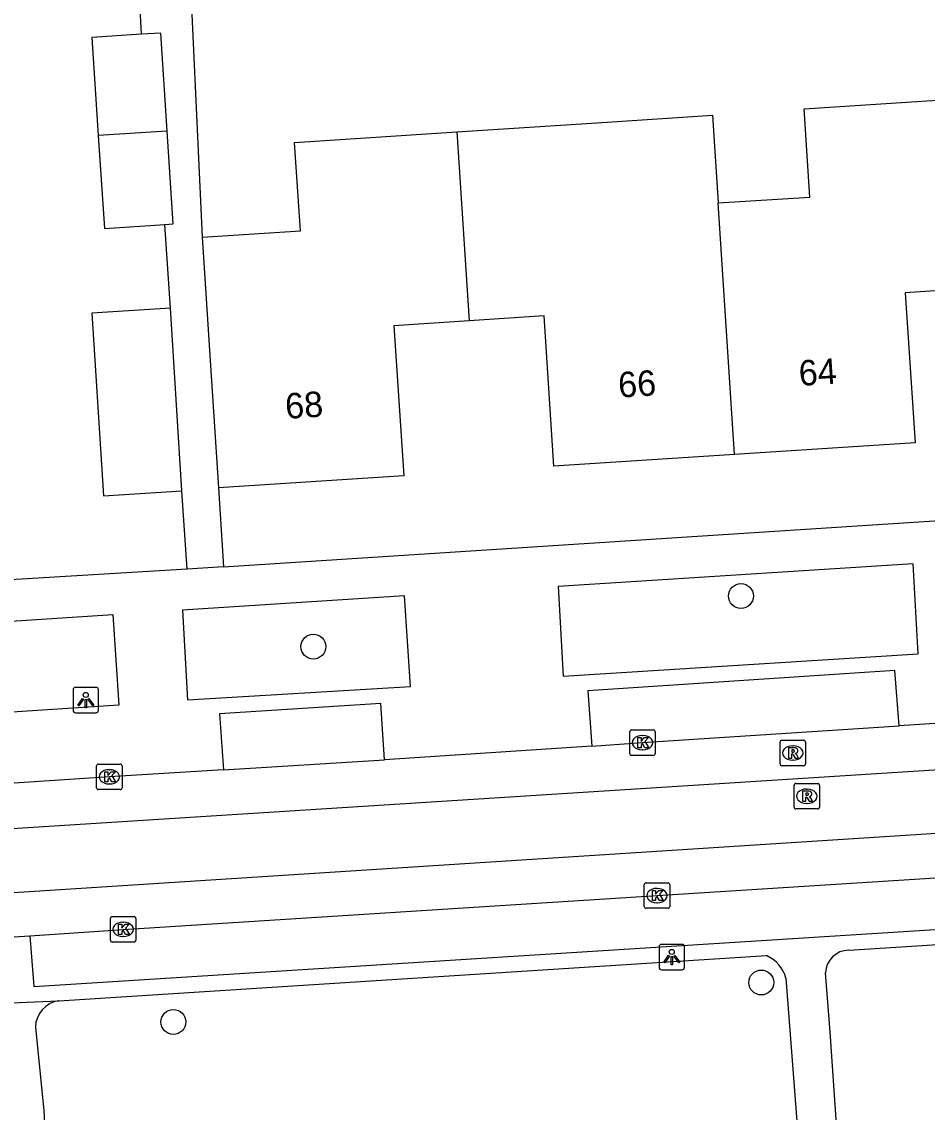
# Model space of a CAD drawing. Extents: x 159689 to 160786, y 387323 to 388339.
# Drawn here: x 160255.13 to 160290.64, y 388015.99 to 388058.78 of the extents above; entities that cross this region are included whole.
import ezdxf

# ---------------------------------------------------------------- set-up
doc = ezdxf.new("R2010")
doc.units = 0
for name, color, linetype in [('IMGEO_Boom', 7, 'Continuous'), ('IMGEO_Kolk', 7, 'Continuous'), ('IMGEO_Lichtpunt', 7, 'Continuous'), ('IMGEO_Pand', 7, 'Continuous'), ('IMGEO_Pand_nummerreeks', 7, 'Continuous'), ('IMGEO_Rijbaan_lokaal_gesloten', 7, 'Continuous'), ('IMGEO_Rioolput', 7, 'Continuous'), ('IMGEO_Voetpad_open', 7, 'Continuous')]:
    doc.layers.add(name, color=color, linetype=linetype)

msp = doc.modelspace()

# ---------------------------------------------------------------- linework, layer by layer
at = {"layer": 'IMGEO_Boom'}
for centre in [(160283.337, 388036.249), (160266.564, 388034.262), (160284.133, 388021.082), (160261.072, 388019.532)]:
    msp.add_circle(centre, 0.489, dxfattribs=at)
at = {"layer": 'IMGEO_Kolk'}
for p, q in [((160278.972, 388030.068), (160278.972, 388030.92)), ((160279.047, 388030.994), (160279.899, 388030.994)), ((160279.46, 388030.774), (160279.485, 388030.774)), ((160279.973, 388030.92), (160279.973, 388030.068)), ((160279.483, 388030.214), (160279.458, 388030.214)), ((160279.899, 388029.994), (160279.047, 388029.994)), ((160258.063, 388028.727), (160258.063, 388029.579)), ((160258.138, 388029.653), (160258.99, 388029.653)), ((160258.551, 388029.433), (160258.576, 388029.433)), ((160259.064, 388029.579), (160259.064, 388028.727)), ((160258.99, 388028.653), (160258.138, 388028.653)), ((160258.574, 388028.873), (160258.549, 388028.873)), ((160279.544, 388024.068), (160279.544, 388024.92)), ((160279.619, 388024.994), (160280.471, 388024.994)), ((160280.032, 388024.774), (160280.057, 388024.774)), ((160280.545, 388024.92), (160280.545, 388024.068)), ((160280.055, 388024.214), (160280.03, 388024.214)), ((160280.471, 388023.994), (160279.619, 388023.994)), ((160258.602, 388022.741), (160258.602, 388023.593)), ((160258.677, 388023.667), (160259.529, 388023.667)), ((160259.09, 388023.447), (160259.115, 388023.447)), ((160259.603, 388023.593), (160259.603, 388022.741)), ((160259.113, 388022.887), (160259.088, 388022.887)), ((160259.529, 388022.667), (160258.677, 388022.667))]:
    msp.add_line(p, q, dxfattribs=at)
for points in [[(160278.972, 388030.068), (160278.972, 388030.92)], [(160279.047, 388030.994), (160279.899, 388030.994)], [(160279.293, 388030.694), (160279.416, 388030.694), (160279.416, 388030.543), (160279.546, 388030.694), (160279.71, 388030.694), (160279.564, 388030.543), (160279.717, 388030.294), (160279.565, 388030.294), (160279.48, 388030.458), (160279.416, 388030.391), (160279.416, 388030.294), (160279.293, 388030.294), (160279.293, 388030.694)], [(160279.973, 388030.92), (160279.973, 388030.068)], [(160279.899, 388029.994), (160279.047, 388029.994)], [(160258.063, 388028.727), (160258.063, 388029.579)], [(160258.138, 388029.653), (160258.99, 388029.653)], [(160258.384, 388029.353), (160258.507, 388029.353), (160258.507, 388029.202), (160258.637, 388029.353), (160258.801, 388029.353), (160258.655, 388029.202), (160258.808, 388028.953), (160258.656, 388028.953), (160258.571, 388029.117), (160258.507, 388029.05), (160258.507, 388028.953), (160258.384, 388028.953), (160258.384, 388029.353)], [(160259.064, 388029.579), (160259.064, 388028.727)], [(160258.99, 388028.653), (160258.138, 388028.653)], [(160279.544, 388024.068), (160279.544, 388024.92)], [(160279.619, 388024.994), (160280.471, 388024.994)], [(160279.865, 388024.694), (160279.988, 388024.694), (160279.988, 388024.543), (160280.118, 388024.694), (160280.282, 388024.694), (160280.136, 388024.543), (160280.289, 388024.294), (160280.137, 388024.294), (160280.052, 388024.458), (160279.988, 388024.391), (160279.988, 388024.294), (160279.865, 388024.294), (160279.865, 388024.694)], [(160280.545, 388024.92), (160280.545, 388024.068)], [(160280.471, 388023.994), (160279.619, 388023.994)], [(160258.602, 388022.741), (160258.602, 388023.593)], [(160258.677, 388023.667), (160259.529, 388023.667)], [(160258.923, 388023.367), (160259.046, 388023.367), (160259.046, 388023.216), (160259.176, 388023.367), (160259.34, 388023.367), (160259.194, 388023.216), (160259.347, 388022.967), (160259.195, 388022.967), (160259.11, 388023.131), (160259.046, 388023.064), (160259.046, 388022.967), (160258.923, 388022.967), (160258.923, 388023.367)], [(160259.603, 388023.593), (160259.603, 388022.741)], [(160259.529, 388022.667), (160258.677, 388022.667)]]:
    msp.add_lwpolyline(points, dxfattribs=at)
for centre, start, end in [((160279.049, 388030.918), 91.552, 178.448), ((160279.049, 388030.918), 91.552, 178.448), ((160279.897, 388030.918), 1.552, 88.448), ((160279.897, 388030.918), 1.552, 88.448), ((160279.049, 388030.07), 181.552, 268.448), ((160279.049, 388030.07), 181.552, 268.448), ((160279.897, 388030.07), 271.552, 358.448), ((160279.897, 388030.07), 271.552, 358.448), ((160258.14, 388029.577), 91.552, 178.448), ((160258.14, 388029.577), 91.552, 178.448), ((160258.988, 388029.577), 1.552, 88.448), ((160258.988, 388029.577), 1.552, 88.448), ((160258.14, 388028.729), 181.552, 268.448), ((160258.14, 388028.729), 181.552, 268.448), ((160258.988, 388028.729), 271.552, 358.448), ((160258.988, 388028.729), 271.552, 358.448), ((160279.621, 388024.918), 91.552, 178.448), ((160279.621, 388024.918), 91.552, 178.448), ((160280.469, 388024.918), 1.552, 88.448), ((160280.469, 388024.918), 1.552, 88.448), ((160279.621, 388024.07), 181.552, 268.448), ((160279.621, 388024.07), 181.552, 268.448), ((160280.469, 388024.07), 271.552, 358.448), ((160280.469, 388024.07), 271.552, 358.448), ((160258.679, 388023.591), 91.552, 178.448), ((160258.679, 388023.591), 91.552, 178.448), ((160259.527, 388023.591), 1.552, 88.448), ((160259.527, 388023.591), 1.552, 88.448), ((160258.679, 388022.743), 181.552, 268.448), ((160258.679, 388022.743), 181.552, 268.448), ((160259.527, 388022.743), 271.552, 358.448), ((160259.527, 388022.743), 271.552, 358.448)]:
    msp.add_arc(centre, 0.0765, start, end, dxfattribs=at)
for centre, major_axis, ratio, start_param, end_param in [((160279.459, 388030.494), (-0.387, 0.002), 0.722429, 4.712389, 7.853982), ((160279.484, 388030.494), (-0.39, 0.002), 0.717154, 1.570796, 4.712389), ((160258.55, 388029.153), (-0.387, 0.002), 0.722429, 4.712389, 7.853982), ((160258.575, 388029.153), (-0.39, 0.002), 0.717154, 1.570796, 4.712389), ((160280.031, 388024.494), (-0.387, 0.002), 0.722429, 4.712389, 7.853982), ((160280.056, 388024.494), (-0.39, 0.002), 0.717154, 1.570796, 4.712389), ((160259.089, 388023.167), (-0.387, 0.002), 0.722429, 4.712389, 7.853982), ((160259.114, 388023.167), (-0.39, 0.002), 0.717154, 1.570796, 4.712389)]:
    msp.add_ellipse(centre, major_axis=major_axis, ratio=ratio, start_param=start_param, end_param=end_param, dxfattribs=at)
at = {"layer": 'IMGEO_Lichtpunt'}
for p, q in [((160257.137, 388032.568), (160257.137, 388031.761)), ((160257.137, 388032.568), (160257.137, 388031.761)), ((160258.039, 388032.663), (160257.231, 388032.663)), ((160258.039, 388032.663), (160257.231, 388032.663)), ((160258.133, 388031.761), (160258.133, 388032.568)), ((160258.133, 388031.761), (160258.133, 388032.568)), ((160257.231, 388031.667), (160258.039, 388031.667)), ((160257.231, 388031.667), (160258.039, 388031.667)), ((160280.123, 388022.484), (160280.123, 388021.677)), ((160280.123, 388022.484), (160280.123, 388021.677)), ((160281.025, 388022.579), (160280.217, 388022.579)), ((160281.025, 388022.579), (160280.217, 388022.579)), ((160281.119, 388021.677), (160281.119, 388022.484)), ((160281.119, 388021.677), (160281.119, 388022.484)), ((160280.217, 388021.583), (160281.025, 388021.583)), ((160280.217, 388021.583), (160281.025, 388021.583))]:
    msp.add_line(p, q, dxfattribs=at)
for points in [[(160257.511, 388032.232), (160257.55, 388032.204), (160257.362, 388031.942), (160257.324, 388031.969), (160257.511, 388032.232)], [(160257.613, 388032.184), (160257.66, 388032.184), (160257.66, 388031.862), (160257.613, 388031.862), (160257.613, 388032.184)], [(160257.723, 388032.204), (160257.761, 388032.231), (160257.948, 388031.969), (160257.909, 388031.941), (160257.723, 388032.204)], [(160280.497, 388022.148), (160280.536, 388022.12), (160280.348, 388021.858), (160280.31, 388021.885), (160280.497, 388022.148)], [(160280.599, 388022.1), (160280.646, 388022.1), (160280.646, 388021.778), (160280.599, 388021.778), (160280.599, 388022.1)], [(160280.709, 388022.12), (160280.747, 388022.147), (160280.934, 388021.885), (160280.895, 388021.857), (160280.709, 388022.12)]]:
    msp.add_lwpolyline(points, dxfattribs=at)
for centre in [(160257.636, 388032.366), (160280.622, 388022.282)]:
    msp.add_circle(centre, 0.0994, dxfattribs=at)
for centre, start, end in [((160257.231, 388032.568), 90, 180), ((160257.231, 388032.568), 90, 180), ((160258.039, 388032.568), 0, 90), ((160258.039, 388032.568), 0, 90), ((160257.231, 388031.761), 180, 270), ((160257.231, 388031.761), 180, 270), ((160258.039, 388031.761), 270, 0), ((160258.039, 388031.761), 270, 360), ((160280.217, 388022.484), 90, 180), ((160280.217, 388022.484), 90, 180), ((160281.025, 388022.484), 0, 90), ((160281.025, 388022.484), 0, 90), ((160280.217, 388021.677), 180, 270), ((160280.217, 388021.677), 180, 270), ((160281.025, 388021.677), 270, 0), ((160281.025, 388021.677), 270, 360)]:
    msp.add_arc(centre, 0.0946, start, end, dxfattribs=at)
at = {"layer": 'IMGEO_Pand'}
for points in [[(160259.824, 388058.292), (160257.874, 388058.163), (160258.128, 388054.325)], [(160260.829, 388054.497), (160260.575, 388058.341), (160259.824, 388058.292)], [(160282.441, 388051.673), (160286.037, 388051.907), (160285.812, 388055.369), (160292.23, 388055.786)], [(160272.192, 388054.462), (160278.093, 388054.845), (160282.217, 388055.113), (160282.441, 388051.673)], [(160260.829, 388054.497), (160258.128, 388054.325)], [(160258.128, 388054.325), (160258.369, 388050.674), (160260.738, 388050.83)], [(160260.738, 388050.83), (160261.07, 388050.852), (160260.829, 388054.497)], [(160262.203, 388050.335), (160266.054, 388050.585), (160265.829, 388054.048), (160272.192, 388054.462)], [(160272.192, 388054.462), (160272.67, 388047.05)], [(160283.082, 388041.799), (160282.441, 388051.673)], [(160262.203, 388050.335), (160262.518, 388045.489), (160262.843, 388040.499)], [(160292.718, 388048.337), (160289.781, 388048.146), (160290.163, 388042.259), (160283.082, 388041.799)], [(160260.954, 388047.55), (160257.874, 388047.354), (160258.33, 388040.177), (160261.41, 388040.373)], [(160261.41, 388040.373), (160260.954, 388047.55)], [(160272.67, 388047.05), (160269.724, 388046.858), (160270.107, 388040.971), (160262.843, 388040.499)], [(160283.082, 388041.799), (160275.998, 388041.338), (160275.614, 388047.241), (160272.67, 388047.05)]]:
    msp.add_lwpolyline(points, dxfattribs=at)
at = {"layer": 'IMGEO_Rijbaan_lokaal_gesloten'}
for points in [[(160245.491, 388026.537), (160290.916, 388029.427), (160338.317, 388032.462), (160338.195, 388034.165)], [(160297.65, 388031.683), (160297.399, 388031.668), (160289.544, 388031.148)], [(160277.493, 388030.35), (160279.473, 388030.494), (160289.544, 388031.148)], [(160277.493, 388030.35), (160269.356, 388029.816)], [(160338.592, 388028.187), (160338.462, 388029.906), (160303.208, 388027.708), (160245.653, 388024.011)], [(160263.039, 388029.425), (160269.356, 388029.816)], [(160263.039, 388029.425), (160258.564, 388029.153), (160245.382, 388028.282)], [(160255.446, 388022.909), (160259.103, 388023.167), (160280.045, 388024.494), (160297.975, 388025.628), (160338.592, 388028.187)], [(160245.738, 388022.293), (160255.446, 388022.909)]]:
    msp.add_lwpolyline(points, dxfattribs=at)
at = {"layer": 'IMGEO_Rioolput'}
for p, q in [((160284.943, 388030.588), (160285.795, 388030.588)), ((160284.868, 388029.662), (160284.868, 388030.514)), ((160285.356, 388030.368), (160285.381, 388030.368)), ((160285.869, 388030.514), (160285.869, 388029.662)), ((160285.379, 388029.808), (160285.354, 388029.808)), ((160285.795, 388029.588), (160284.943, 388029.588)), ((160285.493, 388028.892), (160286.345, 388028.892)), ((160285.418, 388027.966), (160285.418, 388028.818)), ((160285.906, 388028.672), (160285.931, 388028.672)), ((160286.419, 388028.818), (160286.419, 388027.966)), ((160285.929, 388028.112), (160285.904, 388028.112)), ((160286.345, 388027.892), (160285.493, 388027.892))]:
    msp.add_line(p, q, dxfattribs=at)
for points in [[(160284.943, 388030.588), (160285.795, 388030.588)], [(160284.868, 388029.662), (160284.868, 388030.514)], [(160285.457, 388030.286), (160285.205, 388030.288), (160285.205, 388029.888)], [(160285.383, 388030.207), (160285.329, 388030.207), (160285.329, 388030.126)], [(160285.869, 388030.514), (160285.869, 388029.662)], [(160285.205, 388029.888), (160285.329, 388029.888), (160285.329, 388030.05), (160285.34, 388030.05)], [(160285.329, 388030.126), (160285.381, 388030.126)], [(160285.387, 388030.021), (160285.458, 388029.888), (160285.598, 388029.888), (160285.533, 388030.014)], [(160285.795, 388029.588), (160284.943, 388029.588)], [(160285.493, 388028.892), (160286.345, 388028.892)], [(160285.418, 388027.966), (160285.418, 388028.818)], [(160286.007, 388028.59), (160285.755, 388028.592), (160285.755, 388028.192)], [(160285.933, 388028.511), (160285.879, 388028.511), (160285.879, 388028.43)], [(160286.419, 388028.818), (160286.419, 388027.966)], [(160285.755, 388028.192), (160285.879, 388028.192), (160285.879, 388028.354), (160285.89, 388028.354)], [(160285.879, 388028.43), (160285.931, 388028.43)], [(160285.937, 388028.325), (160286.008, 388028.192), (160286.148, 388028.192), (160286.083, 388028.318)], [(160286.345, 388027.892), (160285.493, 388027.892)]]:
    msp.add_lwpolyline(points, dxfattribs=at)
for centre, radius, start, end in [((160284.945, 388030.512), 0.0765, 91.552, 178.448), ((160284.945, 388030.512), 0.0765, 91.552, 178.448), ((160285.793, 388030.512), 0.0765, 1.552, 88.448), ((160285.793, 388030.512), 0.0765, 1.552, 88.448), ((160285.389, 388030.111), 0.0964, 77.0061, 93.1865), ((160285.403, 388030.168), 0.0378, 276.6634, 79.6772), ((160285.456, 388030.176), 0.109, 350.3612, 89.416), ((160285.339, 388029.997), 0.0533, 26.0293, 88.6989), ((160285.365, 388030.315), 0.19, 274.7715, 282.9687), ((160285.454, 388030.176), 0.112, 277.5842, 350.9817), ((160285.438, 388029.961), 0.108, 29.5134, 73.7905), ((160284.945, 388029.664), 0.0765, 181.552, 268.448), ((160284.945, 388029.664), 0.0765, 181.552, 268.448), ((160285.793, 388029.664), 0.0765, 271.552, 358.448), ((160285.793, 388029.664), 0.0765, 271.552, 358.448), ((160285.495, 388028.816), 0.0765, 91.552, 178.448), ((160285.495, 388028.816), 0.0765, 91.552, 178.448), ((160286.343, 388028.816), 0.0765, 1.552, 88.448), ((160286.343, 388028.816), 0.0765, 1.552, 88.448), ((160285.939, 388028.415), 0.0964, 77.0061, 93.1865), ((160285.953, 388028.472), 0.0378, 276.6634, 79.6772), ((160286.006, 388028.48), 0.109, 350.3612, 89.416), ((160286.004, 388028.48), 0.112, 277.5842, 350.9817), ((160285.889, 388028.301), 0.0533, 26.0293, 88.6989), ((160285.915, 388028.619), 0.19, 274.7715, 282.9687), ((160285.988, 388028.265), 0.108, 29.5134, 73.7905), ((160285.495, 388027.968), 0.0765, 181.552, 268.448), ((160285.495, 388027.968), 0.0765, 181.552, 268.448), ((160286.343, 388027.968), 0.0765, 271.552, 358.448), ((160286.343, 388027.968), 0.0765, 271.552, 358.448)]:
    msp.add_arc(centre, radius, start, end, dxfattribs=at)
for centre, major_axis, ratio, start_param, end_param in [((160285.355, 388030.088), (-0.387, 0.002), 0.722429, 4.712389, 7.853982), ((160285.38, 388030.088), (-0.39, 0.002), 0.717154, 1.570796, 4.712389), ((160285.905, 388028.392), (-0.387, 0.002), 0.722429, 4.712389, 7.853982), ((160285.93, 388028.392), (-0.39, 0.002), 0.717154, 1.570796, 4.712389)]:
    msp.add_ellipse(centre, major_axis=major_axis, ratio=ratio, start_param=start_param, end_param=end_param, dxfattribs=at)
at = {"layer": 'IMGEO_Voetpad_open'}
for points in [[(160259.824, 388058.292), (160259.647, 388061.573), (160260.959, 388061.639), (160260.82, 388064.374)], [(160299.486, 388062.953), (160261.729, 388060.499), (160262.203, 388050.335)], [(160260.954, 388047.55), (160260.738, 388050.83)], [(160263.044, 388037.396), (160343.46, 388042.602), (160345.786, 388042.758)], [(160262.843, 388040.499), (160263.044, 388037.396)], [(160261.609, 388037.303), (160261.41, 388040.373)], [(160276.161, 388036.627), (160276.368, 388033.1), (160290.281, 388033.981), (160290.086, 388037.511), (160276.161, 388036.627)], [(160261.609, 388037.303), (160241.021, 388036.065)], [(160263.044, 388037.396), (160261.609, 388037.303)], [(160261.431, 388035.692), (160261.627, 388032.169), (160270.37, 388032.695), (160270.144, 388036.251), (160261.431, 388035.692)], [(160240.946, 388034.364), (160258.701, 388035.517), (160258.933, 388031.971), (160243.756, 388030.974)], [(160289.544, 388031.148), (160289.378, 388033.321), (160277.336, 388032.529), (160277.493, 388030.35)], [(160269.356, 388029.816), (160269.216, 388032.025), (160262.888, 388031.623), (160263.039, 388029.425)], [(160255.446, 388022.909), (160255.596, 388020.929), (160308.738, 388024.292), (160339.136, 388026.242), (160339.005, 388028.206)], [(160287.569, 388022.346), (160315.054, 388024.104)], [(160256.577, 388020.367), (160284.336, 388022.135)], [(160285.101, 388021.248), (160285.801, 388012.069)], [(160287.316, 388012.063), (160286.831, 388019.149), (160286.653, 388021.464)], [(160253.145, 388020.22), (160256.577, 388020.367)], [(160255.663, 388019.33), (160255.986, 388016.052), (160256.326, 388010.05)]]:
    msp.add_lwpolyline(points, dxfattribs=at)
for centre, radius, start, end in [((160283.803, 388020.902), 1.343, 14.9171, 66.6356), ((160287.558, 388021.441), 0.905, 89.2894, 178.5439), ((160256.736, 388019.306), 1.073, 98.5011, 178.7137)]:
    msp.add_arc(centre, radius, start, end, dxfattribs=at)

# ---------------------------------------------------------------- texts
at = {"layer": 'IMGEO_Pand_nummerreeks'}
for s, rotation, p in [('64', 3.7201, (160285.634, 388044.491)), ('66', 3.7201, (160278.551, 388044.03)), ('68', 3.7177, (160265.49, 388043.197))]:
    msp.add_text(s, height=1, rotation=rotation, dxfattribs=at).set_placement(p)

doc.saveas('drawing.dxf')
